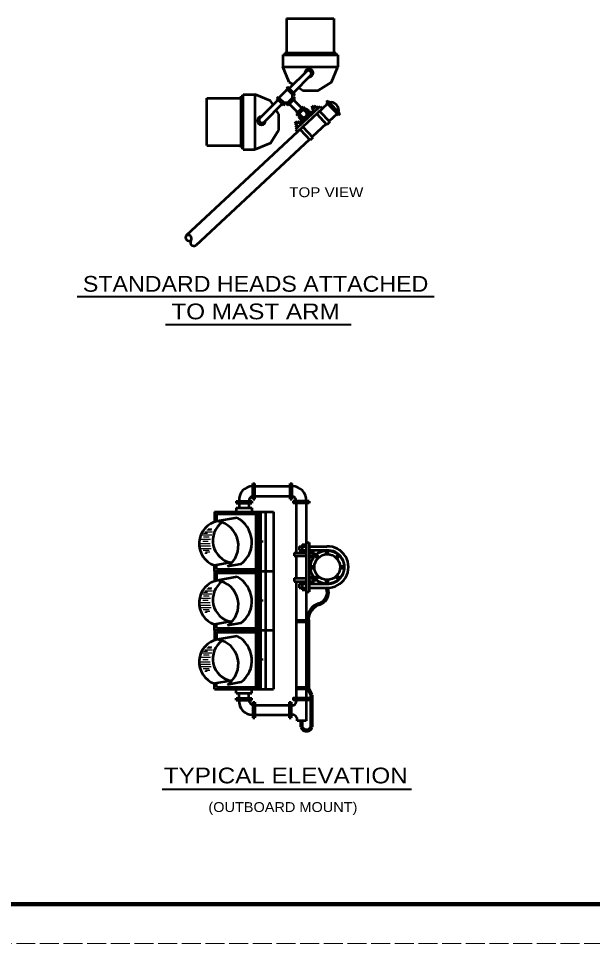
# Model space of a CAD drawing. Extents: x -286 to 394, y -156 to 284.
# Drawn here: x -36.6 to 109, y -155.6 to 79.2 of the extents above; entities that cross this region are included whole.
import ezdxf
from ezdxf.enums import TextEntityAlignment as Align

# ---------------------------------------------------------------- set-up
doc = ezdxf.new("R2010")
doc.units = 0
doc.header["$LTSCALE"] = 0.8
doc.linetypes.add('LONG_DASHED', pattern=[7.5, 6, -1.5])
doc.layers.add('1', color=7, linetype='Continuous', lineweight=53)
doc.layers.add('61', color=7, linetype='Continuous', lineweight=35)

msp = doc.modelspace()

# ---------------------------------------------------------------- linework, layer by layer
at = {"layer": '1'}
for p, q in [((31.4024, 79.2132), (31.4024, 70.4632)), ((31.4024, 79.2132), (43.4024, 79.2132)), ((43.4024, 79.2132), (43.4024, 70.4632)), ((30.9024, 70.4632), (43.9024, 70.4632)), ((30.9024, 70.4632), (30.9024, 69.9632)), ((43.9024, 70.4632), (43.9024, 69.9632)), ((30.4024, 69.9632), (44.4024, 69.9632)), ((30.4024, 69.9632), (30.4024, 66.9632)), ((44.4024, 69.9632), (44.4024, 66.9632)), ((30.4024, 66.9632), (44.4024, 66.9632)), ((32.0102, 63.0828), (30.4024, 66.9632)), ((36.4024, 65.7733), (32.0579, 61.4067)), ((42.7946, 63.0828), (44.4024, 66.9632)), ((37.4656, 64.7155), (33.1211, 60.3487)), ((31.528, 61.2287), (29.4122, 59.1019)), ((31.7033, 61.7595), (31.3507, 61.405)), ((33.1228, 59.6416), (31.3507, 61.405)), ((33.4755, 59.9961), (31.7033, 61.7595)), ((33.068, 62.4219), (32.0102, 63.0828)), ((35.4024, 60.9632), (34.3727, 61.6067)), ((11.1523, 46.9631), (11.1524, 58.9632)), ((11.1524, 58.9632), (19.9024, 58.9632)), ((19.9024, 46.4632), (19.9023, 59.4631)), ((19.9023, 59.4631), (20.4024, 59.4631)), ((20.4024, 45.9632), (20.4024, 59.9632)), ((20.4024, 59.9632), (23.4024, 59.9632)), ((23.4024, 45.9632), (23.4024, 59.9632)), ((27.2827, 58.3552), (23.4024, 59.9632)), ((29.2347, 59.2785), (28.8821, 58.9242)), ((30.6541, 57.1607), (28.8821, 58.9242)), ((31.0068, 57.5151), (29.2347, 59.2785)), ((33.1238, 59.2882), (31.3604, 57.5157)), ((33.4782, 58.9356), (31.7148, 57.1632)), ((33.4755, 59.9961), (33.1228, 59.6416)), ((33.1238, 59.2882), (33.4782, 58.9356)), ((29.2369, 58.5711), (24.6524, 53.9632)), ((30.3, 57.513), (25.7156, 52.9052)), ((27.9537, 57.2814), (27.2827, 58.3552)), ((30.6541, 57.1607), (31.0068, 57.5151)), ((31.3604, 57.5157), (31.7148, 57.1632)), ((32.0674, 57.5176), (34.1942, 55.4017)), ((33.1255, 58.5812), (35.2523, 56.4654)), ((35.6049, 56.8197), (33.8416, 55.0472)), ((41.7944, 57.583), (34.1804, 50.4828)), ((35.9593, 56.4671), (34.196, 54.6947)), ((35.6049, 56.8197), (35.9593, 56.4671)), ((37.7218, 56.5918), (38.2702, 57.1034)), ((37.7218, 56.5918), (38.0629, 56.226)), ((38.8857, 56.9932), (37.7887, 55.9703)), ((37.8923, 56.4091), (38.4408, 56.9207)), ((37.9898, 56.6711), (38.1727, 56.8417)), ((38.1603, 56.4884), (38.3432, 56.6589)), ((38.2702, 57.1034), (38.6114, 56.7375)), ((38.7028, 56.8228), (39.2143, 56.2742)), ((38.8857, 56.9932), (39.3972, 56.4447)), ((39.8677, 56.8834), (40.4369, 56.3171)), ((41.8192, 58.2897), (41.4535, 57.9487)), ((41.4535, 57.9487), (44.5224, 54.6575)), ((41.8192, 58.2897), (44.8881, 54.9985)), ((29.4024, 54.9632), (28.77, 55.9752)), ((29.4024, 50.9632), (29.4024, 54.9632)), ((33.8416, 55.0472), (34.196, 54.6947)), ((34.5486, 55.0491), (35.2875, 54.3141)), ((35.6068, 56.1127), (36.3156, 55.4077)), ((36.7186, 55.4176), (37.4817, 54.6585)), ((37.0316, 55.8115), (37.8477, 54.9997)), ((37.7886, 55.9703), (38.3001, 55.4217)), ((37.9714, 56.1408), (38.483, 55.5922)), ((39.0302, 55.0053), (41.5875, 52.2625)), ((39.7616, 55.6873), (42.3188, 52.9445)), ((44.1815, 55.0232), (42.1484, 53.1273)), ((44.8881, 54.9985), (44.5224, 54.6575)), ((33.485, 52.6409), (34.0334, 53.1525)), ((33.485, 52.6409), (33.8261, 52.2751)), ((33.5517, 52.0194), (34.0632, 51.4708)), ((34.6488, 53.0423), (33.5518, 52.0193)), ((35.5904, 52.8948), (33.6332, 51.0697)), ((33.6555, 52.4582), (34.2039, 52.9697)), ((33.7346, 52.1899), (34.2462, 51.6412)), ((33.7529, 52.7202), (33.9358, 52.8907)), ((33.9235, 52.5375), (34.1064, 52.708)), ((34.0334, 53.1525), (34.3746, 52.7866)), ((34.4659, 52.8719), (34.9775, 52.3233)), ((34.6488, 53.0423), (35.1603, 52.4937)), ((34.8757, 53.6058), (35.5904, 52.8948)), ((35.2283, 53.9602), (35.9374, 53.2548)), ((35.5247, 51.7363), (38.082, 48.9935)), ((41.4171, 52.4453), (37.9116, 49.1763)), ((42.3188, 52.9445), (41.5875, 52.2625)), ((34.1805, 50.4827), (5.9582, 24.1649)), ((33.6228, 51.06), (34.1922, 50.4937)), ((34.7933, 51.0544), (37.3507, 48.3116)), ((37.1803, 48.4944), (8.3452, 21.6052)), ((11.1523, 46.9631), (19.9023, 46.9631)), ((38.082, 48.9935), (37.3507, 48.3116)), ((19.9024, 46.4632), (20.4024, 46.4631)), ((20.4024, 45.9632), (23.4024, 45.9632)), ((22.826, -42.7785), (22.826, -38.7785)), ((22.826, -38.7785), (23.326, -38.7785)), ((23.326, -42.7785), (23.326, -38.7785)), ((23.326, -39.5285), (32.326, -39.5285)), ((32.326, -42.7785), (32.326, -38.7785)), ((32.326, -42.7785), (32.326, -38.7785)), ((32.326, -38.7785), (32.826, -38.7785)), ((32.826, -42.7785), (32.826, -38.7785)), ((23.326, -42.0285), (32.326, -42.0285)), ((18.576, -43.2785), (22.576, -43.2785)), ((18.576, -43.2785), (18.576, -43.7785)), ((18.576, -43.7785), (22.576, -43.7785)), ((19.326, -43.7785), (19.326, -45.0285)), ((21.826, -43.7785), (21.826, -45.0285)), ((22.576, -43.2785), (22.576, -43.7785)), ((22.826, -42.7785), (23.326, -42.7785)), ((32.326, -42.7785), (32.826, -42.7785)), ((37.076, -43.2785), (33.076, -43.2785)), ((33.076, -43.2785), (33.076, -43.7785)), ((37.076, -43.7785), (33.076, -43.7785)), ((33.826, -43.7785), (33.826, -56.3785)), ((37.076, -43.2785), (37.076, -43.7785)), ((13.076, -46.0285), (28.076, -46.0285)), ((13.076, -46.0285), (13.076, -48.5944)), ((13.576, -46.5285), (24.076, -46.5285)), ((13.576, -46.5285), (13.576, -48.4608)), ((18.576, -45.0285), (22.576, -45.0285)), ((18.576, -45.0285), (18.576, -46.0285)), ((22.576, -45.0285), (22.576, -46.0285)), ((23.576, -46.5285), (23.576, -60.5285)), ((24.076, -46.5285), (24.076, -60.5285)), ((26.076, -46.0285), (26.076, -91.0285)), ((28.076, -46.0285), (28.076, -91.0285)), ((18.826, -47.5285), (13.902, -48.3967)), ((25.076, -53.2785), (24.076, -53.2785)), ((25.076, -53.7785), (24.076, -53.7785)), ((25.076, -53.2785), (25.076, -53.7785)), ((36.326, -53.7785), (37.076, -53.7785)), ((37.076, -53.7785), (37.076, -66.2785)), ((34.576, -54.7785), (34.576, -55.7785)), ((34.576, -54.7785), (36.326, -54.7785)), ((34.576, -55.7785), (36.326, -55.7785)), ((35.326, -54.2785), (36.326, -54.2785)), ((35.326, -54.2785), (35.326, -56.2785)), ((35.326, -56.2785), (36.326, -56.2785)), ((37.076, -54.7785), (41.576, -54.7785)), ((37.076, -55.7785), (41.576, -55.7785)), ((37.076, -56.0285), (38.076, -56.0285)), ((38.076, -56.0285), (38.076, -57.5285)), ((41.4597, -56.7775), (41.4597, -55.7997)), ((41.9597, -56.7775), (41.9597, -55.7997)), ((33.326, -56.3785), (36.326, -56.3785)), ((33.326, -56.3785), (33.326, -57.1785)), ((33.326, -57.1785), (36.326, -57.1785)), ((33.826, -57.1785), (33.826, -62.8785)), ((37.076, -56.3785), (38.426, -56.3785)), ((37.076, -57.1785), (38.426, -57.1785)), ((37.076, -57.5285), (38.076, -57.5285)), ((38.426, -56.3785), (38.426, -57.1785)), ((39.2233, -57.8952), (38.5351, -57.2072)), ((39.5768, -57.5417), (38.8887, -56.8536)), ((43.8154, -57.5583), (44.5245, -56.8532)), ((44.168, -57.9129), (44.8771, -57.2077)), ((17.247, -58.8807), (13.076, -59.6162)), ((13.076, -61.0285), (13.076, -59.6162)), ((13.076, -61.0285), (28.076, -61.0285)), ((13.076, -61.0285), (13.076, -63.6202)), ((13.576, -60.5285), (13.576, -59.528)), ((13.576, -60.5285), (24.076, -60.5285)), ((19.826, -59.2785), (16.3792, -59.8862)), ((37.4597, -59.7785), (38.4373, -59.7785)), ((37.4597, -60.2785), (38.4373, -60.2785)), ((44.9373, -59.7785), (45.9596, -59.7785)), ((44.9373, -60.2785), (45.9596, -60.2785)), ((13.576, -61.5285), (24.076, -61.5285)), ((13.576, -61.5285), (13.576, -63.4694)), ((18.826, -62.5285), (13.902, -63.3967)), ((23.576, -61.5285), (23.576, -75.5285)), ((24.076, -61.5285), (24.076, -75.5285)), ((33.326, -62.8785), (36.326, -62.8785)), ((33.326, -62.8785), (33.326, -63.6785)), ((37.076, -62.5285), (38.076, -62.5285)), ((37.076, -62.8785), (38.426, -62.8785)), ((38.076, -62.5285), (38.076, -64.0285)), ((38.426, -62.8785), (38.426, -63.6785)), ((38.4977, -62.8468), (39.2066, -62.1418)), ((38.8502, -63.2014), (39.5592, -62.4964)), ((41.4597, -64.2997), (41.4597, -63.2773)), ((41.9597, -64.2997), (41.9597, -63.2773)), ((44.5496, -63.2201), (43.8201, -62.4908)), ((44.903, -62.8665), (44.1735, -62.1372)), ((33.326, -63.6785), (36.326, -63.6785)), ((33.826, -63.6785), (33.826, -93.2998)), ((34.576, -64.2785), (34.576, -65.2785)), ((34.576, -64.2785), (36.326, -64.2785)), ((34.576, -65.2785), (36.326, -65.2785)), ((35.326, -63.7785), (35.326, -65.7785)), ((35.326, -63.7785), (36.326, -63.7785)), ((37.076, -63.6785), (38.426, -63.6785)), ((37.076, -64.0285), (38.076, -64.0285)), ((37.076, -64.2785), (41.576, -64.2785)), ((37.076, -65.2785), (41.576, -65.2785)), ((35.326, -65.7785), (36.326, -65.7785)), ((36.326, -66.2785), (37.076, -66.2785)), ((25.076, -68.2785), (24.076, -68.2785)), ((25.076, -68.7785), (24.076, -68.7785)), ((25.076, -68.2785), (25.076, -68.7785)), ((17.247, -73.8807), (13.076, -74.6162)), ((13.076, -76.0285), (13.076, -74.6162)), ((13.576, -75.5285), (13.576, -74.528)), ((19.826, -74.2785), (16.3792, -74.8863)), ((13.076, -76.0285), (28.076, -76.0285)), ((13.076, -76.0285), (13.076, -78.6202)), ((13.576, -75.5285), (24.076, -75.5285)), ((13.576, -76.5285), (24.076, -76.5285)), ((13.576, -76.5285), (13.576, -78.4694)), ((23.576, -76.5285), (23.576, -90.5285)), ((24.076, -76.5285), (24.076, -90.5285)), ((18.826, -77.5285), (13.902, -78.3967)), ((25.076, -83.2785), (24.076, -83.2785)), ((25.076, -83.7785), (24.076, -83.7785)), ((25.076, -83.2785), (25.076, -83.7785)), ((17.247, -88.8807), (13.076, -89.6162)), ((13.076, -91.0285), (13.076, -89.6162)), ((13.076, -91.0285), (28.076, -91.0285)), ((13.576, -90.5285), (13.576, -89.528)), ((13.576, -90.5285), (24.076, -90.5285)), ((19.826, -89.2785), (16.3792, -89.8863)), ((18.576, -92.0495), (18.576, -91.0495)), ((22.576, -92.0495), (22.576, -91.0495)), ((18.576, -92.0495), (22.576, -92.0495)), ((18.576, -93.2995), (22.576, -93.2995)), ((18.576, -93.7995), (18.576, -93.2995)), ((18.576, -93.7995), (22.576, -93.7995)), ((19.326, -93.2995), (19.326, -92.0495)), ((21.826, -93.2995), (21.826, -92.0495)), ((22.576, -93.7995), (22.576, -93.2995)), ((37.0757, -93.8021), (33.0757, -93.7993)), ((36.3257, -93.8016), (36.3222, -99.0514)), ((37.076, -93.3022), (37.0757, -93.8021)), ((22.826, -94.2995), (22.826, -98.2995)), ((22.826, -94.2995), (23.326, -94.2995)), ((23.326, -94.2995), (23.326, -98.2995)), ((23.326, -95.0495), (32.0757, -95.0495)), ((32.0757, -94.2993), (32.0757, -98.2993)), ((32.0757, -94.2993), (32.5757, -94.2993)), ((32.5757, -94.2993), (32.5757, -98.2993)), ((22.826, -98.2995), (23.326, -98.2995)), ((23.326, -97.5495), (32.0757, -97.5495)), ((32.0757, -98.2993), (32.5757, -98.2993)), ((36.3222, -99.0514), (34.0722, -99.0514))]:
    msp.add_line(p, q, dxfattribs=at)
at = {"layer": '1', "lineweight": 40}
for p, q in [((-21.7203, 8.6631), (68.8126, 8.6631)), ((0.6614, 1.5671), (47.734, 1.5671)), ((-0.1827, -116.3658), (63.0451, -116.3658))]:
    msp.add_line(p, q, dxfattribs=at)
at = {"layer": '1', "lineweight": 90}
for p, q in [((24.576, -46.0285), (24.576, -53.2785)), ((24.576, -53.7785), (24.576, -68.2785)), ((24.576, -68.7785), (24.576, -83.2785)), ((24.576, -83.7785), (24.576, -91.0285))]:
    msp.add_line(p, q, dxfattribs=at)
at = {"layer": '1', "lineweight": 25}
for p, q in [((10.299, -51.4111), (11.3644, -51.4111)), ((10.6637, -51.0767), (12.5599, -51.0767)), ((11.1803, -50.5598), (12.3417, -50.5598)), ((11.5147, -50.3167), (12.4612, -50.3167)), ((9.5392, -52.9312), (12.1253, -52.9312)), ((10.0559, -51.8367), (12.4334, -51.8367)), ((10.1774, -53.4479), (11.515, -53.4479)), ((10.3294, -52.3231), (11.7278, -52.3231)), ((9.4177, -54.664), (12.0922, -54.664)), ((9.4177, -55.3024), (12.2336, -55.3024)), ((9.5088, -54.056), (12.033, -54.056)), ((10.2498, -55.7762), (11.7624, -55.7762)), ((10.8189, -56.197), (11.9368, -56.197)), ((10.6457, -56.4692), (11.2396, -56.4692)), ((11.1803, -65.5598), (12.3417, -65.5598)), ((11.5147, -65.3167), (12.4612, -65.3167)), ((9.5392, -67.9312), (12.1253, -67.9312)), ((10.0559, -66.8367), (12.4334, -66.8367)), ((10.299, -66.4111), (11.3644, -66.4111)), ((10.3294, -67.3231), (11.7278, -67.3231)), ((10.6637, -66.0767), (12.5599, -66.0767)), ((9.4177, -69.664), (12.0922, -69.664)), ((9.4177, -70.3024), (12.2336, -70.3024)), ((9.5088, -69.056), (12.033, -69.056)), ((10.1774, -68.4479), (11.515, -68.4479)), ((10.2498, -70.7763), (11.7624, -70.7763)), ((10.6457, -71.4693), (11.2396, -71.4693)), ((10.8189, -71.197), (11.9368, -71.197)), ((10.0559, -81.8367), (12.4334, -81.8367)), ((10.299, -81.4111), (11.3644, -81.4111)), ((10.6637, -81.0767), (12.5599, -81.0767)), ((11.1803, -80.5598), (12.3417, -80.5598)), ((11.5147, -80.3167), (12.4612, -80.3167)), ((9.5088, -84.056), (12.033, -84.056)), ((9.5392, -82.9312), (12.1253, -82.9312)), ((10.1774, -83.4479), (11.515, -83.4479)), ((10.3294, -82.3231), (11.7278, -82.3231)), ((9.4177, -84.664), (12.0922, -84.664)), ((9.4177, -85.3024), (12.2336, -85.3024)), ((10.2498, -85.7762), (11.7624, -85.7762)), ((10.6457, -86.4693), (11.2396, -86.4693)), ((10.8189, -86.197), (11.9368, -86.197))]:
    msp.add_line(p, q, dxfattribs=at)
at = {"layer": '1', "lineweight": 158}
for p, q in [((36.826, -73.802), (33.8384, -73.7998)), ((36.8262, -90.802), (33.826, -90.7998))]:
    msp.add_line(p, q, dxfattribs=at)
at = {"layer": '1', "lineweight": 106}
for p, q in [((37.6972, -100.5514), (37.6972, -92.5514)), ((35.1972, -100.5514), (35.1972, -99.0514))]:
    msp.add_line(p, q, dxfattribs=at)
at = {"layer": '1'}
for points in [[(35.4024, 60.9632), (39.4024, 60.9632), (42.7946, 63.0828)], [(39.8496, 56.8666), (37.8477, 54.9997), (35.5904, 52.8948)], [(29.4024, 50.9632), (27.2827, 47.5709), (23.4024, 45.9632)], [(36.326, -43.7785), (36.326, -73.8017), (36.326, -90.8017), (36.326, -93.3017)], [(37.076, -93.3022), (33.076, -93.2993), (33.0757, -93.7993)]]:
    msp.add_lwpolyline(points, dxfattribs=at)
at = {"layer": '1', "lineweight": 106}
msp.add_lwpolyline([(36.826, -73.8017), (36.826, -90.8017), (37.6972, -92.5514)], dxfattribs=at)
at = {"layer": '1'}
for centre, radius in [((41.7097, -60.0497), 4.25), ((41.6873, -60.0274), 3.25)]:
    msp.add_circle(centre, radius, dxfattribs=at)
for centre, radius, start, end in [((37.0852, 65.3964), 1.0357, 271.53559, 178.75707), ((36.9341, 65.2445), 0.7499, 315.13282, 135.15983), ((33.2737, 59.4635), 0.4829, 132.78877, 226.89174), ((31.1841, 57.363), 0.4829, 43.09034, 137.19331), ((42.5689, 55.9123), 2.0528, 344.51342, 101.48659), ((25.0328, 53.2823), 1.0357, 91.53442, 358.7447), ((35.752, 54.5215), 1.2675, 157.40371, 226.25762), ((35.9581, 54.7146), 1.0357, 182.10453, 89.27128), ((35.802, 54.8613), 0.7499, 226.74884, 46.77586), ((36.1289, 54.9217), 1.2675, 44.58462, 113.43853), ((25.184, 53.4341), 0.75, 135.13507, 315.14405), ((6.6776, 23.6393), 0.8909, 143.84232, 302.15542), ((6.3958, 23.3565), 0.8909, 328.05031, 126.36341), ((7.871, 22.3595), 0.8909, 143.84232, 302.15542), ((22.7617, -42.9768), 3.4489, 88.93093, 185.01894), ((32.8903, -42.9768), 3.4489, 354.98106, 91.06907), ((23.2154, -43.3651), 1.3921, 106.24508, 176.43531), ((32.4366, -43.3651), 1.3921, 3.56469, 73.75492), ((15.0065, -54.1182), 5.827, 100.9259, 250.65279), ((18.3335, -53.3206), 5.6653, 125.42652, 258.94304), ((12.8452, -54.6364), 6.3285, 303.94628, 80.38748), ((15.5926, -53.7212), 6.986, 307.29917, 62.42986), ((41.8203, -60.0285), 5.2557, 267.33556, 92.66444), ((41.8191, -60.0285), 4.2569, 266.72684, 93.27315), ((15.5926, -68.7212), 6.986, 307.29917, 62.42986), ((15.0065, -69.1182), 5.827, 100.9259, 250.65279), ((18.3335, -68.3206), 5.6653, 125.42652, 258.94304), ((12.8452, -69.6364), 6.3285, 303.94628, 80.38748), ((15.0065, -84.1182), 5.827, 100.9259, 250.65279), ((18.3335, -83.3206), 5.6653, 125.42652, 258.94304), ((12.8452, -84.6364), 6.3285, 303.94628, 80.38748), ((15.5926, -83.7212), 6.986, 307.29917, 62.42986), ((22.7617, -94.1012), 3.4489, 174.98106, 271.06907), ((23.2154, -93.7129), 1.3921, 183.56469, 253.75492), ((32.8652, -94.089), 1.003, 253.22176, 16.76297), ((32.8688, -98.7538), 1.2396, 346.10771, 103.67892)]:
    msp.add_arc(centre, radius, start, end, dxfattribs=at)
at = {"layer": '1', "lineweight": 106}
for centre, radius, start, end in [((38.7002, -66.4723), 3.1138, 279.16279, 22.54388), ((41, -73.3387), 4.1996, 115.43994, 186.32898), ((36.4472, -100.2702), 1.2812, 192.68038, 347.31962)]:
    msp.add_arc(centre, radius, start, end, dxfattribs=at)
at = {"layer": '61', "lineweight": 158}
msp.add_line((382.7109, -145.5772), (-256.3491, -145.5572), dxfattribs=at)
at = {"layer": '61', "linetype": 'LONG_DASHED', "lineweight": 13}
msp.add_line((393.6509, -155.5572), (-286.4091, -155.5772), dxfattribs=at)

# ---------------------------------------------------------------- texts
at = {"layer": '1'}
for s, height, width, p in [('TOP VIEW', 2.5, 1.15, (41.4589, 33.8662)), ('STANDARD HEADS ATTACHED', 4, 1.1, (23.5278, 9.8598)), ('TO MAST ARM', 4, 1.15, (23.5278, 2.8598)), ('TYPICAL ELEVATION', 4, 1.15, (31.1707, -114.9344)), ('(OUTBOARD MOUNT)', 2.5, 1.1, (30.4549, -122.1954))]:
    msp.add_text(s, height=height, dxfattribs=dict(at, width=width)).set_placement(p, align=Align.CENTER)

doc.saveas('drawing.dxf')
